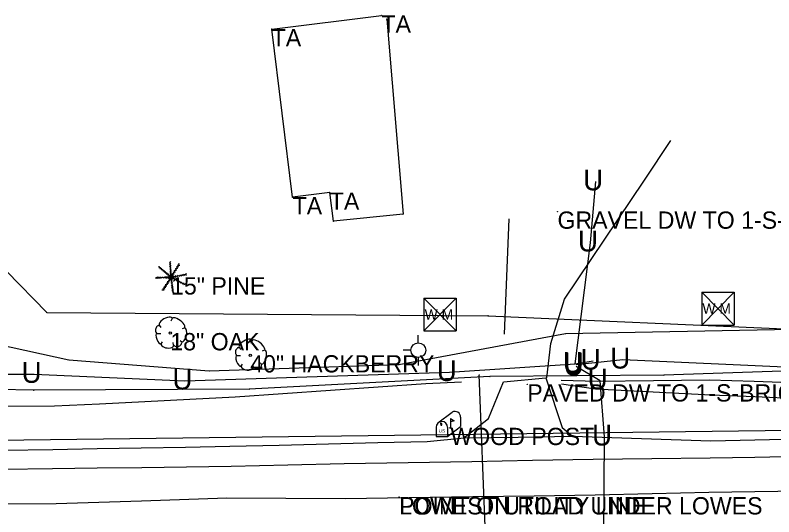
# Model space of a CAD drawing. Extents: x 1800653 to 1804042, y 522635 to 523313.
# Drawn here: x 1802796.8 to 1803016.3, y 522987.6 to 523132.7 of the extents above; entities that cross this region are included whole.
import ezdxf

# ---------------------------------------------------------------- set-up
doc = ezdxf.new("R2010")
doc.units = 0
for name, color, linetype in [('Default', 7, 'Continuous'), ('S_BASELINE', 7, 'Continuous'), ('S_BUILDING', 7, 'Continuous'), ('S_BUILDING_ANNOT', 7, 'Continuous'), ('S_DITCHLINE', 7, 'Continuous'), ('S_DRIVEWAY', 7, 'Continuous'), ('S_EDGE_PAVEMENT', 7, 'Continuous'), ('S_ELECTRIC_UTILITIES_ANNOT', 7, 'Continuous'), ('S_FIBER_OPTIC_CABLE', 7, 'Continuous'), ('S_GAS_UTILITIES', 7, 'Continuous'), ('S_MAILBOX', 7, 'Continuous'), ('S_MAILBOX_ANNOT', 7, 'Continuous'), ('S_MSC_PT_SYM', 7, 'Continuous'), ('S_PAVEMENT_CROWN', 7, 'Continuous'), ('S_SANITARY_SEWER', 7, 'Continuous'), ('S_SHOULDER', 7, 'Continuous'), ('S_STR_PT_SYM', 7, 'Continuous'), ('S_SURVEY_TEXT_ANNOT', 7, 'Continuous'), ('S_TREE', 7, 'Continuous'), ('S_TREE_ANNOT', 7, 'Continuous'), ('S_UNDERGROUND_CABLE', 7, 'Continuous'), ('S_UTILITY_POLE', 7, 'Continuous'), ('S_UTL_PT_SYM', 7, 'Continuous'), ('S_WATER_UTILITIES', 7, 'Continuous')]:
    doc.layers.add(name, color=color, linetype=linetype)

msp = doc.modelspace()

# ---------------------------------------------------------------- linework, layer by layer
at = {"layer": 'S_BASELINE'}
msp.add_line((1802220.63, 523002.66), (1803097.96, 523013.6), dxfattribs=at)
at = {"layer": 'S_BUILDING'}
for p, q in [((1802871.04, 523128.71), (1802902.8, 523132.66)), ((1802904.34, 523131.51), (1802909.05, 523075.18)), ((1802877.1, 523080.08), (1802871.04, 523128.71)), ((1802887.86, 523081.42), (1802877.1, 523080.08)), ((1802888.89, 523073.09), (1802887.86, 523081.42)), ((1802909.05, 523075.18), (1802888.89, 523073.09))]:
    msp.add_line(p, q, dxfattribs=at)
at = {"layer": 'S_DITCHLINE'}
for points in [[(1802954.76, 523027.19), (1802965.25, 523026.85), (1802981.47, 523027.06), (1802997.7, 523027.27), (1803010.63, 523026.85), (1803023.56, 523026.42), (1803036.49, 523025.99), (1803049.42, 523025.57), (1803063.54, 523025.91), (1803077.66, 523026.26), (1803091.77, 523026.61), (1803105.89, 523026.96), (1803118.74, 523026.75), (1803131.59, 523026.53), (1803144.45, 523026.32), (1803157.3, 523026.11), (1803171.75, 523026.51), (1803186.19, 523026.9), (1803200.64, 523027.3), (1803215.09, 523027.7), (1803229.41, 523027.72), (1803243.73, 523027.74), (1803258.05, 523027.76), (1803272.38, 523027.78)], [(1802793.4, 523019.66), (1802808.18, 523019.7), (1802821.26, 523020.35), (1802834.33, 523020.99), (1802847.41, 523021.64), (1802860.48, 523022.29), (1802874.26, 523023.27), (1802888.04, 523024.24), (1802901.83, 523025.22), (1802915.61, 523026.2), (1802925.98, 523026.68)], [(1802954.86, 523026.08), (1802964.7, 523024.61), (1802981.39, 523023.77), (1802998.08, 523022.92), (1803010.85, 523022.39), (1803023.62, 523021.85), (1803036.38, 523021.31), (1803049.15, 523020.77), (1803063.29, 523021.48), (1803077.43, 523022.18), (1803091.58, 523022.88), (1803105.72, 523023.58), (1803118.57, 523023.74), (1803131.43, 523023.9), (1803144.29, 523024.05), (1803157.14, 523024.21), (1803171.66, 523024.43), (1803186.19, 523024.65), (1803200.71, 523024.88), (1803215.23, 523025.1), (1803229.37, 523025.17), (1803243.51, 523025.24), (1803257.65, 523025.32), (1803271.78, 523025.39)]]:
    msp.add_lwpolyline(points, dxfattribs=at)
at = {"layer": 'S_DRIVEWAY'}
for points in [[(1802950.61, 523027.84), (1802951.76, 523037.78), (1802955.78, 523050.54), (1802963.47, 523062.03), (1802971.17, 523073.51), (1802978.87, 523085), (1802986.56, 523096.49)], [(1802939.68, 523073.8), (1802939, 523057.14), (1802938.32, 523040.47)], [(1802926.67, 523010.44), (1802933.78, 523016.09), (1802938.08, 523026.66), (1802950.35, 523027.79), (1802953.56, 523018.06), (1802955.04, 523013.49), (1802958.05, 523010.97)]]:
    msp.add_lwpolyline(points, dxfattribs=at)
at = {"layer": 'S_EDGE_PAVEMENT'}
msp.add_lwpolyline([(1802793.3, 523001.37), (1802807.68, 523001.62), (1802820.59, 523001.78), (1802833.49, 523001.94), (1802846.39, 523002.1), (1802859.3, 523002.26), (1802875.67, 523002.64), (1802892.04, 523003.03), (1802910.49, 523003.32), (1802928.94, 523003.62), (1802946.5, 523003.98), (1802964.06, 523004.33), (1802980.98, 523004.5), (1802997.9, 523004.67), (1803010.82, 523004.9), (1803023.74, 523005.13)], dxfattribs=at)
at = {"layer": 'S_FIBER_OPTIC_CABLE'}
for p, q in [((1802934.18, 523028.23), (1802864.56, 523024.56)), ((1802984.52, 523028.61), (1802934.18, 523028.23)), ((1803025.5, 523029.94), (1802984.52, 523028.61)), ((1802802.2, 523024.23), (1802683.7, 523026.61)), ((1802864.56, 523024.56), (1802802.2, 523024.23))]:
    msp.add_line(p, q, dxfattribs=at)
at = {"layer": 'S_GAS_UTILITIES'}
for p, q in [((1802794.31, 523058.67), (1802806.01, 523046.72)), ((1802806.01, 523046.72), (1802933.65, 523045.78)), ((1802933.65, 523045.78), (1803078.29, 523039.38))]:
    msp.add_line(p, q, dxfattribs=at)
at = {"layer": 'S_MAILBOX'}
for p, q in [((1802919.15, 523014.8), (1802923.28, 523017.91)), ((1802922.76, 523016.09), (1802922.76, 523013.38)), ((1802925.71, 523016.44), (1802925.71, 523013.72)), ((1802918.59, 523013.53), (1802918.59, 523010.82)), ((1802921.92, 523010.82), (1802925.71, 523013.72)), ((1802921.92, 523013.53), (1802921.92, 523010.82)), ((1802918.59, 523010.82), (1802921.92, 523010.82))]:
    msp.add_line(p, q, dxfattribs=at)
for points in [[(1802919.78, 523014.65), (1802920, 523014.51), (1802920, 523014.12), (1802920.3, 523014.12), (1802920.3, 523014.48), (1802920.11, 523014.73), (1802919.78, 523014.67)], [(1802922.76, 523016.09), (1802923.87, 523015.43), (1802922.76, 523015.08)]]:
    msp.add_lwpolyline(points, dxfattribs=at)
for centre, end in [((1802924.05, 523016.44), 117.5718), ((1802920.25, 523013.53), 180)]:
    msp.add_arc(centre, 1.66, 0, end, dxfattribs=at)
msp.add_ellipse((1802922.76, 523013.38), major_axis=(0.145, 0.132), ratio=0.564646, dxfattribs=at)
at = {"layer": 'S_MSC_PT_SYM'}
for points in [[(1802953.74, 523075.94), (1802953.74, 523075.99), (1802953.74, 523075.94), (1802953.69, 523075.94), (1802953.74, 523075.94), (1802953.74, 523075.89), (1802953.74, 523075.94), (1802953.79, 523075.94)], [(1802944.99, 523025.97), (1802944.99, 523026.02), (1802944.99, 523025.97), (1802944.94, 523025.97), (1802944.99, 523025.97), (1802944.99, 523025.92), (1802944.99, 523025.97), (1802945.04, 523025.97)], [(1802907.92, 522993.32), (1802907.92, 522993.37), (1802907.92, 522993.32), (1802907.87, 522993.32), (1802907.92, 522993.32), (1802907.92, 522993.27), (1802907.92, 522993.32), (1802907.97, 522993.32)]]:
    msp.add_lwpolyline(points, dxfattribs=at)
at = {"layer": 'S_PAVEMENT_CROWN'}
msp.add_lwpolyline([(1802794.02, 522991.35), (1802808.65, 522991.45), (1802833.37, 522992.27), (1802858.09, 522993.08), (1802875.18, 522993.01), (1802892.27, 522992.94), (1802910.76, 522993.2), (1802929.25, 522993.47), (1802946.96, 522993.71), (1802964.67, 522993.95), (1802981.09, 522994.36), (1802997.51, 522994.76), (1803010.81, 522994.95), (1803024.11, 522995.13), (1803037.42, 522995.32), (1803050.72, 522995.5), (1803064.06, 522995.56), (1803077.39, 522995.61), (1803090.73, 522995.66), (1803104.06, 522995.72), (1803117.45, 522996.1), (1803130.84, 522996.49), (1803144.23, 522996.88)], dxfattribs=at)
at = {"layer": 'S_SANITARY_SEWER'}
msp.add_line((1802934.16, 522951.6), (1802931.11, 523028.65), dxfattribs=at)
at = {"layer": 'S_SHOULDER'}
msp.add_lwpolyline([(1802793.4, 523006.87), (1802807.72, 523007.13), (1802820.52, 523007.36), (1802833.33, 523007.59), (1802846.14, 523007.81), (1802858.94, 523008.04), (1802873.22, 523008.39), (1802887.51, 523008.73), (1802901.79, 523009.08), (1802916.07, 523009.43), (1802926.71, 523010.44), (1802942.38, 523010.7), (1802958.05, 523010.97), (1802978.06, 523010.3), (1802998.06, 523009.62), (1803010.87, 523009.91), (1803023.68, 523010.2)], dxfattribs=at)
at = {"layer": 'S_STR_PT_SYM'}
for points in [[(1802902.8, 523132.66), (1802902.8, 523132.71), (1802902.8, 523132.66), (1802902.75, 523132.66), (1802902.8, 523132.66), (1802902.8, 523132.61), (1802902.8, 523132.66), (1802902.85, 523132.66)], [(1802904.34, 523131.51), (1802904.34, 523131.56), (1802904.34, 523131.51), (1802904.29, 523131.51), (1802904.34, 523131.51), (1802904.34, 523131.46), (1802904.34, 523131.51), (1802904.39, 523131.51)], [(1802871.04, 523128.71), (1802871.04, 523128.76), (1802871.04, 523128.71), (1802870.99, 523128.71), (1802871.04, 523128.71), (1802871.04, 523128.66), (1802871.04, 523128.71), (1802871.09, 523128.71)], [(1802887.86, 523081.42), (1802887.86, 523081.47), (1802887.86, 523081.42), (1802887.81, 523081.42), (1802887.86, 523081.42), (1802887.86, 523081.37), (1802887.86, 523081.42), (1802887.91, 523081.42)], [(1802877.1, 523080.08), (1802877.1, 523080.13), (1802877.1, 523080.08), (1802877.05, 523080.08), (1802877.1, 523080.08), (1802877.1, 523080.03), (1802877.1, 523080.08), (1802877.15, 523080.08)], [(1802909.05, 523075.18), (1802909.05, 523075.23), (1802909.05, 523075.18), (1802909, 523075.18), (1802909.05, 523075.18), (1802909.05, 523075.13), (1802909.05, 523075.18), (1802909.1, 523075.18)], [(1802888.89, 523073.09), (1802888.89, 523073.14), (1802888.89, 523073.09), (1802888.84, 523073.09), (1802888.89, 523073.09), (1802888.89, 523073.04), (1802888.89, 523073.09), (1802888.94, 523073.09)]]:
    msp.add_lwpolyline(points, dxfattribs=at)
at = {"layer": 'S_TREE'}
for p, q in [((1802841.67, 523061), (1802841.45, 523061.2)), ((1802841.93, 523056.92), (1802841.66, 523061.35)), ((1802841.67, 523061.24), (1802841.86, 523061.48)), ((1802841.7, 523060.77), (1802841.89, 523061)), ((1802844.24, 523060.57), (1802844.16, 523060.85)), ((1802838.64, 523059.66), (1802838.35, 523059.62)), ((1802841.93, 523056.92), (1802838.46, 523059.83)), ((1802838.5, 523059.8), (1802838.5, 523060.1)), ((1802838.99, 523059.38), (1802838.69, 523059.36)), ((1802838.82, 523059.55), (1802838.82, 523059.85)), ((1802839.35, 523059.06), (1802839.06, 523059.03)), ((1802839.17, 523059.26), (1802839.17, 523059.56)), ((1802839.81, 523058.68), (1802839.51, 523058.66)), ((1802839.59, 523058.9), (1802839.59, 523059.2)), ((1802840, 523058.57), (1802840, 523058.87)), ((1802840.32, 523058.28), (1802840.32, 523058.58)), ((1802841.71, 523060.43), (1802841.48, 523060.63)), ((1802841.73, 523059.86), (1802841.51, 523060.06)), ((1802841.76, 523059.2), (1802841.54, 523059.4)), ((1802841.8, 523058.61), (1802841.57, 523058.81)), ((1802841.73, 523060.17), (1802841.92, 523060.4)), ((1802841.77, 523059.46), (1802841.96, 523059.69)), ((1802841.83, 523058.89), (1802842.02, 523059.12)), ((1802841.85, 523058.32), (1802842.04, 523058.55)), ((1802841.93, 523056.92), (1802844.27, 523060.6)), ((1802843.03, 523058.69), (1802842.94, 523058.98)), ((1802843.24, 523058.93), (1802843.54, 523058.97)), ((1802843.41, 523059.26), (1802843.32, 523059.54)), ((1802843.57, 523059.47), (1802843.86, 523059.51)), ((1802843.7, 523059.77), (1802843.61, 523060.06)), ((1802843.89, 523059.96), (1802844.19, 523060)), ((1802844, 523060.23), (1802843.91, 523060.51)), ((1802844.13, 523060.39), (1802844.43, 523060.43)), ((1802837.56, 523056.7), (1802837.43, 523056.43)), ((1802841.93, 523056.92), (1802837.48, 523056.7)), ((1802837.71, 523056.73), (1802837.54, 523056.97)), ((1802837.91, 523056.73), (1802837.77, 523056.46)), ((1802838.1, 523056.75), (1802837.93, 523057)), ((1802838.25, 523056.75), (1802838.12, 523056.48)), ((1802838.5, 523056.75), (1802838.33, 523057)), ((1802838.67, 523056.76), (1802838.54, 523056.49)), ((1802838.9, 523056.78), (1802838.73, 523057.03)), ((1802839.18, 523056.79), (1802839.05, 523056.52)), ((1802839.46, 523056.79), (1802839.3, 523057.04)), ((1802841.93, 523056.92), (1802839.55, 523053.14)), ((1802839.74, 523056.81), (1802839.61, 523056.54)), ((1802840.02, 523056.83), (1802839.85, 523057.08)), ((1802840.17, 523058.35), (1802839.87, 523058.33)), ((1802840.23, 523056.83), (1802840.09, 523056.56)), ((1802840.51, 523058.09), (1802840.21, 523058.07)), ((1802840.5, 523056.84), (1802840.33, 523057.09)), ((1802840.85, 523057.79), (1802840.55, 523057.77)), ((1802840.7, 523056.86), (1802840.56, 523056.59)), ((1802840.69, 523057.98), (1802840.69, 523058.28)), ((1802840.94, 523056.88), (1802840.77, 523057.13)), ((1802841.22, 523057.5), (1802840.92, 523057.47)), ((1802841.15, 523056.86), (1802841.02, 523056.6)), ((1802841.06, 523057.68), (1802841.06, 523057.98)), ((1802841.27, 523056.92), (1802841.1, 523057.17)), ((1802841.58, 523057.2), (1802841.28, 523057.18)), ((1802841.6, 523056.42), (1802841.3, 523056.39)), ((1802841.41, 523057.36), (1802841.41, 523057.66)), ((1802841.54, 523056.88), (1802841.41, 523056.61)), ((1802841.84, 523058.04), (1802841.61, 523058.24)), ((1802841.85, 523057.42), (1802841.63, 523057.62)), ((1802841.72, 523056.59), (1802841.8, 523056.3)), ((1802841.87, 523057.65), (1802842.06, 523057.88)), ((1802841.93, 523056.92), (1802846.35, 523057.78)), ((1802841.93, 523056.92), (1802845.84, 523054.87)), ((1802841.93, 523056.92), (1802842.46, 523052.54)), ((1802842.01, 523056.49), (1802842.26, 523056.33)), ((1802842.26, 523056.74), (1802842.52, 523056.88)), ((1802842.37, 523057.67), (1802842.28, 523057.96)), ((1802842.28, 523057.41), (1802842.57, 523057.45)), ((1802842.3, 523057), (1802842.51, 523057.22)), ((1802842.44, 523056.64), (1802842.51, 523056.35)), ((1802842.55, 523057.03), (1802842.8, 523056.87)), ((1802842.56, 523057.87), (1802842.86, 523057.91)), ((1802842.73, 523058.2), (1802842.65, 523058.49)), ((1802842.7, 523057.06), (1802842.91, 523057.28)), ((1802842.73, 523056.51), (1802843, 523056.65)), ((1802842.9, 523058.41), (1802843.19, 523058.46)), ((1802843.02, 523056.34), (1802843.09, 523056.04)), ((1802843.06, 523057.11), (1802843.32, 523056.95)), ((1802843.23, 523057.16), (1802843.44, 523057.38)), ((1802843.29, 523056.21), (1802843.56, 523056.35)), ((1802843.58, 523057.23), (1802843.83, 523057.06)), ((1802843.8, 523057.29), (1802844, 523057.51)), ((1802844.19, 523057.35), (1802844.44, 523057.19)), ((1802844.43, 523057.43), (1802844.64, 523057.65)), ((1802844.77, 523057.46), (1802845.02, 523057.3)), ((1802845.03, 523057.52), (1802845.23, 523057.75)), ((1802845.28, 523057.57), (1802845.53, 523057.41)), ((1802845.51, 523057.63), (1802845.71, 523057.85)), ((1802845.7, 523057.66), (1802845.96, 523057.5)), ((1802845.96, 523057.72), (1802846.16, 523057.94)), ((1802846.11, 523057.72), (1802846.36, 523057.56)), ((1802846.18, 523057.77), (1802846.38, 523057.99)), ((1802840.27, 523054.32), (1802839.97, 523054.28)), ((1802840.19, 523054.14), (1802840.26, 523053.84)), ((1802840.57, 523054.77), (1802840.27, 523054.73)), ((1802840.43, 523054.52), (1802840.51, 523054.23)), ((1802840.83, 523055.19), (1802840.53, 523055.15)), ((1802840.72, 523054.98), (1802840.79, 523054.69)), ((1802841.08, 523055.61), (1802840.79, 523055.57)), ((1802840.97, 523055.41), (1802841.05, 523055.12)), ((1802841.36, 523056.05), (1802841.06, 523056.02)), ((1802841.23, 523055.82), (1802841.31, 523055.53)), ((1802841.51, 523056.26), (1802841.58, 523055.97)), ((1802841.99, 523056.24), (1802841.79, 523056.01)), ((1802842.05, 523055.66), (1802841.86, 523055.43)), ((1802842.14, 523055.1), (1802841.94, 523054.87)), ((1802842.21, 523054.53), (1802842.01, 523054.3)), ((1802842.04, 523055.94), (1802842.3, 523055.78)), ((1802842.13, 523055.37), (1802842.38, 523055.21)), ((1802842.19, 523054.82), (1802842.45, 523054.66)), ((1802842.26, 523054.31), (1802842.52, 523054.15)), ((1802843.55, 523056.06), (1802843.63, 523055.77)), ((1802843.84, 523055.92), (1802844.11, 523056.06)), ((1802844.08, 523055.79), (1802844.15, 523055.5)), ((1802844.33, 523055.66), (1802844.59, 523055.8)), ((1802844.61, 523055.49), (1802844.68, 523055.2)), ((1802844.86, 523055.39), (1802845.13, 523055.53)), ((1802845.13, 523055.23), (1802845.2, 523054.94)), ((1802845.41, 523055.12), (1802845.68, 523055.26)), ((1802845.62, 523054.98), (1802845.69, 523054.69)), ((1802845.81, 523054.91), (1802846.07, 523055.05)), ((1802839.58, 523053.23), (1802839.28, 523053.19)), ((1802839.78, 523053.53), (1802839.48, 523053.49)), ((1802839.7, 523053.39), (1802839.78, 523053.1)), ((1802840.03, 523053.94), (1802839.73, 523053.91)), ((1802839.93, 523053.74), (1802840, 523053.44)), ((1802842.27, 523054.07), (1802842.08, 523053.84)), ((1802842.31, 523053.69), (1802842.12, 523053.46)), ((1802842.37, 523053.25), (1802842.17, 523053.02)), ((1802842.42, 523052.83), (1802842.22, 523052.6)), ((1802842.3, 523053.88), (1802842.55, 523053.72)), ((1802842.34, 523053.47), (1802842.6, 523053.31)), ((1802842.41, 523053.01), (1802842.66, 523052.85)), ((1802842.44, 523052.66), (1802842.7, 523052.51)), ((1802842.28, 523045.03), (1802841.89, 523044.18)), ((1802838.48, 523043.02), (1802838.98, 523042.43)), ((1802845.84, 523042.24), (1802845.18, 523041.97)), ((1802837.82, 523040.69), (1802838.95, 523040.69)), ((1802838.98, 523037.51), (1802839.45, 523038.21)), ((1802842.67, 523037.24), (1802842.59, 523038.02)), ((1802845.07, 523038.13), (1802844.6, 523038.56)), ((1802861.59, 523036.61), (1802862.09, 523036.03)), ((1802865.38, 523038.63), (1802865, 523037.78)), ((1802868.95, 523035.84), (1802868.29, 523035.57)), ((1802860.93, 523034.29), (1802862.05, 523034.29)), ((1802862.09, 523031.11), (1802862.56, 523031.81)), ((1802865.77, 523030.84), (1802865.69, 523031.61)), ((1802868.17, 523031.73), (1802867.71, 523032.16))]:
    msp.add_line(p, q, dxfattribs=at)
for centre in [(1802841.72, 523040.78), (1802864.83, 523034.38)]:
    msp.add_circle(centre, 0.341, dxfattribs=at)
for centre, major_axis, ratio, start_param, end_param in [((1802840.38, 523043.99), (1.86, 1.08), 0.471018, 0, 3.141593), ((1802844.04, 523043.66), (-1.81, 1.36), 0.405113, 3.141593, 6.283186), ((1802838.15, 523041.87), (0.31, 1.03), 0.646762, 0, 3.141593), ((1802845.39, 523040.25), (0.46, 2.04), 0.482994, 3.141593, 6.283185), ((1802838.45, 523039.22), (-0.61, 1.6), 0.420543, 6.283185, 9.424777), ((1802863.49, 523037.59), (1.86, 1.08), 0.471018, 0, 3.141593), ((1802867.14, 523037.26), (-1.81, 1.36), 0.405113, 3.141593, 6.283186), ((1802840.91, 523037.44), (-1.83, 0.19), 0.529943, 0, 3.141593), ((1802843.87, 523037.73), (1.09, 0.46), 0.711534, 3.141592, 6.283185), ((1802861.26, 523035.47), (0.31, 1.03), 0.646762, 0, 3.141593), ((1802861.56, 523032.82), (-0.61, 1.6), 0.420543, 6.283185, 9.424777), ((1802868.5, 523033.85), (0.46, 2.04), 0.482994, 3.141593, 6.283185), ((1802864.02, 523031.04), (-1.83, 0.19), 0.529943, 0, 3.141593), ((1802866.98, 523031.33), (1.09, 0.46), 0.711534, 3.141592, 6.283185)]:
    msp.add_ellipse(centre, major_axis=major_axis, ratio=ratio, start_param=start_param, end_param=end_param, dxfattribs=at)
at = {"layer": 'S_UNDERGROUND_CABLE'}
for p, q in [((1802963.28, 523066.91), (1802964.78, 523084.6)), ((1802958.89, 523031.87), (1802963.28, 523066.91)), ((1802958.89, 523031.87), (1802964.05, 523032.75)), ((1802972.62, 523033.05), (1802959.14, 523031.6)), ((1803045.88, 523029.75), (1802972.62, 523033.05)), ((1802922.44, 523029.46), (1802958.89, 523031.87)), ((1802966.07, 523027), (1802959.13, 523031.08)), ((1802747.76, 523028.88), (1802802.31, 523028.93)), ((1802802.31, 523028.93), (1802845.96, 523026.99)), ((1802845.96, 523026.99), (1802922.44, 523029.46)), ((1802967.36, 523010.8), (1802966.07, 523027)), ((1802967.09, 522976.27), (1802967.36, 523010.8))]:
    msp.add_line(p, q, dxfattribs=at)
at = {"layer": 'S_UTILITY_POLE'}
for p, q in [((1802913.47, 523037.93), (1802913.47, 523040.17)), ((1802911.38, 523035.8), (1802909.05, 523035.8)), ((1802913.55, 523031.38), (1802913.55, 523033.7))]:
    msp.add_line(p, q, dxfattribs=at)
msp.add_circle((1802913.47, 523035.82), 2.13, dxfattribs=at)
at = {"layer": 'S_UTL_PT_SYM'}
for points in [[(1802806.01, 523046.72), (1802806.01, 523046.77), (1802806.01, 523046.72), (1802805.96, 523046.72), (1802806.01, 523046.72), (1802806.01, 523046.67), (1802806.01, 523046.72), (1802806.06, 523046.72)], [(1802933.65, 523045.78), (1802933.65, 523045.83), (1802933.65, 523045.78), (1802933.6, 523045.78), (1802933.65, 523045.78), (1802933.65, 523045.73), (1802933.65, 523045.78), (1802933.7, 523045.78)], [(1802956.08, 523040.62), (1802956.08, 523040.67), (1802956.08, 523040.62), (1802956.03, 523040.62), (1802956.08, 523040.62), (1802956.08, 523040.57), (1802956.08, 523040.62), (1802956.13, 523040.62)], [(1802812.37, 523032.99), (1802812.37, 523033.04), (1802812.37, 523032.99), (1802812.32, 523032.99), (1802812.37, 523032.99), (1802812.37, 523032.94), (1802812.37, 523032.99), (1802812.42, 523032.99)], [(1802907.85, 523031.73), (1802907.85, 523031.78), (1802907.85, 523031.73), (1802907.8, 523031.73), (1802907.85, 523031.73), (1802907.85, 523031.68), (1802907.85, 523031.73), (1802907.9, 523031.73)], [(1802853, 523029.87), (1802853, 523029.92), (1802853, 523029.87), (1802852.95, 523029.87), (1802853, 523029.87), (1802853, 523029.82), (1802853, 523029.87), (1802853.05, 523029.87)], [(1802931.11, 523028.65), (1802931.11, 523028.7), (1802931.11, 523028.65), (1802931.06, 523028.65), (1802931.11, 523028.65), (1802931.11, 523028.6), (1802931.11, 523028.65), (1802931.16, 523028.65)], [(1802934.18, 523028.23), (1802934.18, 523028.28), (1802934.18, 523028.23), (1802934.13, 523028.23), (1802934.18, 523028.23), (1802934.18, 523028.18), (1802934.18, 523028.23), (1802934.23, 523028.23)], [(1802984.52, 523028.61), (1802984.52, 523028.66), (1802984.52, 523028.61), (1802984.47, 523028.61), (1802984.52, 523028.61), (1802984.52, 523028.56), (1802984.52, 523028.61), (1802984.57, 523028.61)], [(1802802.2, 523024.23), (1802802.2, 523024.28), (1802802.2, 523024.23), (1802802.15, 523024.23), (1802802.2, 523024.23), (1802802.2, 523024.18), (1802802.2, 523024.23), (1802802.25, 523024.23)], [(1802864.56, 523024.56), (1802864.56, 523024.61), (1802864.56, 523024.56), (1802864.51, 523024.56), (1802864.56, 523024.56), (1802864.56, 523024.51), (1802864.56, 523024.56), (1802864.61, 523024.56)], [(1802907.92, 522993.32), (1802907.92, 522993.37), (1802907.92, 522993.32), (1802907.87, 522993.32), (1802907.92, 522993.32), (1802907.92, 522993.27), (1802907.92, 522993.32), (1802907.97, 522993.32)]]:
    msp.add_lwpolyline(points, dxfattribs=at)
at = {"layer": 'S_WATER_UTILITIES'}
for p, q in [((1802995.47, 523052.58), (1803004.8, 523052.58)), ((1802995.47, 523052.58), (1802995.47, 523043.09)), ((1802995.47, 523052.58), (1803004.8, 523043.09)), ((1803004.8, 523052.58), (1802995.47, 523043.09)), ((1803004.8, 523052.58), (1803004.8, 523043.09)), ((1802915.09, 523050.89), (1802924.43, 523050.89)), ((1802915.09, 523050.89), (1802915.09, 523041.39)), ((1802915.09, 523050.89), (1802924.43, 523041.39)), ((1802924.43, 523050.89), (1802915.09, 523041.39)), ((1802924.43, 523050.89), (1802924.43, 523041.39)), ((1802915.09, 523041.39), (1802924.43, 523041.39)), ((1802956.08, 523040.62), (1803078.38, 523043.05)), ((1802995.47, 523043.09), (1803004.8, 523043.09)), ((1802786.43, 523038.78), (1802812.37, 523032.99)), ((1802907.85, 523031.73), (1802956.08, 523040.62)), ((1802812.37, 523032.99), (1802853, 523029.87)), ((1802853, 523029.87), (1802907.85, 523031.73))]:
    msp.add_line(p, q, dxfattribs=at)

# ---------------------------------------------------------------- texts
at = {"layer": 'Default'}
for p in [(1802961.15, 523082.06), (1802959.65, 523064.37), (1802955.26, 523029.32), (1802955.26, 523029.32), (1802955.5, 523028.53), (1802955.51, 523029.06), (1802960.42, 523030.21), (1802968.99, 523030.51), (1802798.68, 523026.38), (1802918.81, 523026.91), (1802842.33, 523024.44), (1802962.45, 523024.46), (1802963.73, 523008.25)]:
    msp.add_text('U', height=6, dxfattribs=at).set_placement(p)
at = {"layer": 'S_BUILDING_ANNOT'}
for p in [(1802902.8, 523127.66), (1802871.04, 523123.71), (1802887.86, 523076.42), (1802877.1, 523075.08)]:
    msp.add_text('TA', height=5, dxfattribs=at).set_placement(p)
at = {"layer": 'S_ELECTRIC_UTILITIES_ANNOT'}
msp.add_text('LOWEST UTILITY LINE', height=5, dxfattribs=at).set_placement((1802907.92, 522988.32))
at = {"layer": 'S_MAILBOX'}
msp.add_text('US', height=0.96, dxfattribs=at).set_placement((1802919.36, 523012.01))
at = {"layer": 'S_MAILBOX_ANNOT'}
msp.add_text('WOOD POST', height=5, dxfattribs=at).set_placement((1802922.76, 523008.38))
at = {"layer": 'S_SURVEY_TEXT_ANNOT'}
for s, p in [('GRAVEL DW TO 1-S-BRICK', (1802953.74, 523070.94)), ('PAVED DW TO 1-S-BRICK', (1802944.99, 523020.97)), ('POINT ON ROAD UNDER LOWES', (1802907.92, 522988.32))]:
    msp.add_text(s, height=5, dxfattribs=at).set_placement(p)
at = {"layer": 'S_TREE_ANNOT'}
for s, p in [('15" PINE', (1802841.93, 523051.92)), ('18" OAK', (1802841.72, 523035.78)), ('40" HACKBERRY', (1802864.83, 523029.38))]:
    msp.add_text(s, height=5, dxfattribs=at).set_placement(p)
at = {"layer": 'S_WATER_UTILITIES'}
for p in [(1802915.3, 523044.65), (1802995.67, 523046.35)]:
    msp.add_text('W M', height=3, dxfattribs=at).set_placement(p)

doc.saveas('drawing.dxf')
